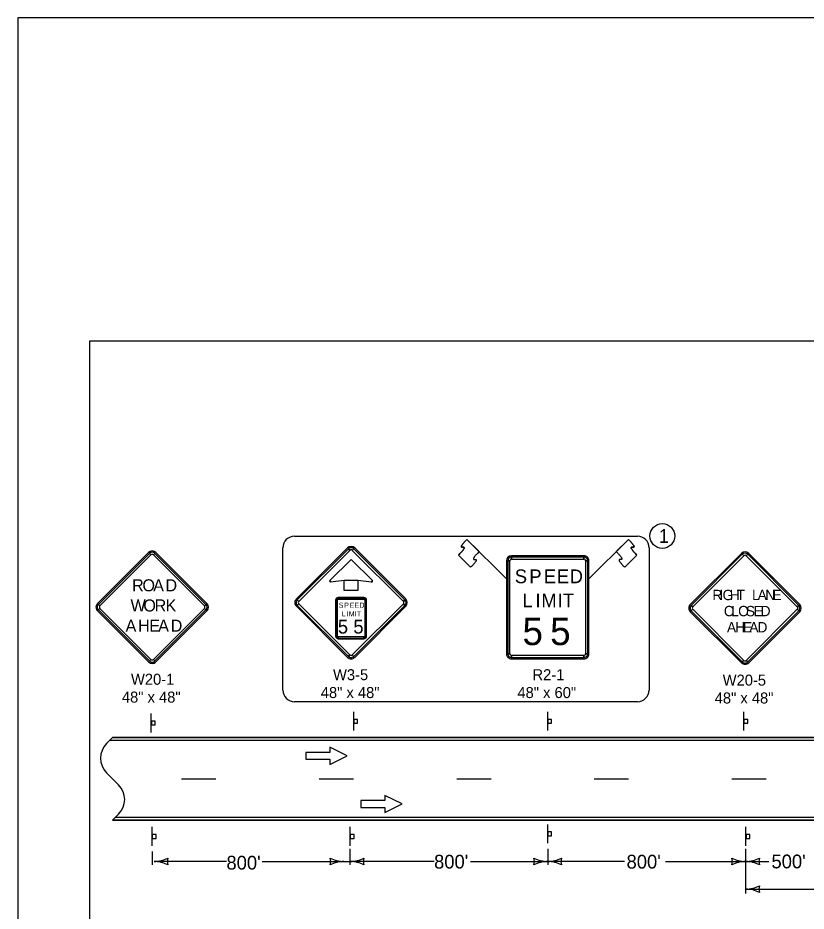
# Model space of a CAD drawing. Extents: x -2135039 to 114557, y -2139150 to -409929.
# Drawn here: x -2131439 to -2130293, y -2137865 to -2136566 of the extents above; entities that cross this region are included whole.
import ezdxf

# ---------------------------------------------------------------- set-up
doc = ezdxf.new("R2010")
doc.units = 0
for name, color, linetype in [('dsnDOTLogo', 7, 'Continuous'), ('dsnStdLabel', 7, 'Continuous'), ('dsnStdLineWork', 7, 'Continuous'), ('dsnStdNote', 7, 'Continuous'), ('dsnStdShading', 7, 'Continuous'), ('Level 1', 7, 'Continuous'), ('StdDimension', 7, 'Continuous')]:
    doc.layers.add(name, color=color, linetype=linetype)

msp = doc.modelspace()

# ---------------------------------------------------------------- linework, layer by layer
at = {"layer": 'dsnDOTLogo'}
msp.add_lwpolyline([(-2131438.9, -2139150.4), (-2128095, -2139150.4), (-2128095, -2136566.4), (-2131438.9, -2136566.4)], close=True, dxfattribs=at)
at = {"layer": 'dsnStdLabel'}
for p, q in [((-2130728.5, -2137382), (-2130785.9, -2137324.7)), ((-2130785.9, -2137324.7), (-2130768.2, -2137342.4)), ((-2130608.5, -2137382), (-2130551.2, -2137324.7)), ((-2130551.2, -2137324.7), (-2130568.9, -2137342.4)), ((-2130959.7, -2137337.2), (-2131034, -2137411.4)), ((-2130958.4, -2137338.5), (-2130956.2, -2137340.7)), ((-2130952.7, -2137340.7), (-2130950.4, -2137338.5)), ((-2130874.9, -2137411.4), (-2130949.1, -2137337.2)), ((-2131248.9, -2137343.8), (-2131323.2, -2137418.1)), ((-2131247.6, -2137345.2), (-2131245.4, -2137347.4)), ((-2131241.9, -2137347.4), (-2131239.6, -2137345.2)), ((-2131164.1, -2137418.1), (-2131238.3, -2137343.8)), ((-2130798.2, -2137347.7), (-2130780.6, -2137365.4)), ((-2130780.6, -2137365.4), (-2130798.2, -2137347.7)), ((-2130616, -2137348.5), (-2130721, -2137348.5)), ((-2130721, -2137353.5), (-2130721, -2137350.4)), ((-2130616, -2137350.4), (-2130616, -2137353.5)), ((-2130538.9, -2137347.7), (-2130556.5, -2137365.4)), ((-2130556.5, -2137365.4), (-2130538.9, -2137347.7)), ((-2130386.9, -2137345.1), (-2130461.2, -2137419.3)), ((-2130385.6, -2137346.4), (-2130383.4, -2137348.6)), ((-2130379.9, -2137348.6), (-2130377.6, -2137346.4)), ((-2130302.1, -2137419.3), (-2130376.3, -2137345.1)), ((-2130728.5, -2137356), (-2130728.5, -2137491)), ((-2130726.7, -2137356), (-2130723.5, -2137356)), ((-2130613.5, -2137356), (-2130610.4, -2137356)), ((-2130608.5, -2137491), (-2130608.5, -2137356)), ((-2130984.4, -2137385.5), (-2130985.3, -2137384.6)), ((-2130984.3, -2137386.7), (-2130984.4, -2137385.5)), ((-2130924.4, -2137385.5), (-2130924.6, -2137386.7)), ((-2130923.5, -2137384.6), (-2130924.4, -2137385.5)), ((-2131030.4, -2137415), (-2131032.6, -2137412.8)), ((-2130976.9, -2137413), (-2130976.9, -2137465.5)), ((-2130976, -2137413), (-2130974.4, -2137413)), ((-2130935.7, -2137409.2), (-2130973.2, -2137409.2)), ((-2130973.2, -2137411.7), (-2130973.2, -2137410.2)), ((-2130935.7, -2137410.2), (-2130935.7, -2137411.7)), ((-2130934.4, -2137413), (-2130932.9, -2137413)), ((-2130931.9, -2137465.5), (-2130931.9, -2137413)), ((-2130876.2, -2137412.8), (-2130878.4, -2137415)), ((-2131323.2, -2137428.7), (-2131248.9, -2137502.9)), ((-2131319.6, -2137421.6), (-2131321.8, -2137419.4)), ((-2131321.8, -2137427.4), (-2131319.6, -2137425.2)), ((-2131238.3, -2137502.9), (-2131164.1, -2137428.7)), ((-2131165.4, -2137419.4), (-2131167.6, -2137421.6)), ((-2131167.6, -2137425.2), (-2131165.4, -2137427.4)), ((-2131034, -2137422), (-2130959.7, -2137496.3)), ((-2131032.6, -2137420.7), (-2131030.4, -2137418.5)), ((-2130949.1, -2137496.3), (-2130874.9, -2137422)), ((-2130878.4, -2137418.5), (-2130876.2, -2137420.7)), ((-2130457.6, -2137422.9), (-2130459.8, -2137420.7)), ((-2130459.8, -2137428.6), (-2130457.6, -2137426.4)), ((-2130303.4, -2137420.7), (-2130305.6, -2137422.9)), ((-2130305.6, -2137426.4), (-2130303.4, -2137428.6)), ((-2130461.2, -2137430), (-2130386.9, -2137504.2)), ((-2130376.3, -2137504.2), (-2130302.1, -2137430)), ((-2130974.4, -2137465.5), (-2130976, -2137465.5)), ((-2130973.2, -2137468.3), (-2130973.2, -2137466.7)), ((-2130935.7, -2137466.7), (-2130935.7, -2137468.3)), ((-2130932.9, -2137465.5), (-2130934.4, -2137465.5)), ((-2130973.2, -2137469.2), (-2130935.7, -2137469.2)), ((-2130956.2, -2137492.8), (-2130958.4, -2137495)), ((-2130950.4, -2137495), (-2130952.7, -2137492.8)), ((-2130723.5, -2137491), (-2130726.7, -2137491)), ((-2130721, -2137496.6), (-2130721, -2137493.5)), ((-2130616, -2137493.5), (-2130616, -2137496.6)), ((-2130610.4, -2137491), (-2130613.5, -2137491)), ((-2131245.4, -2137499.4), (-2131247.6, -2137501.6)), ((-2131239.6, -2137501.6), (-2131241.9, -2137499.4)), ((-2130721, -2137498.5), (-2130616, -2137498.5)), ((-2130383.4, -2137500.7), (-2130385.6, -2137502.9)), ((-2130377.6, -2137502.9), (-2130379.9, -2137500.7)), ((-2131244.9, -2137605.4), (-2131244.9, -2137577.9)), ((-2130950.6, -2137602.9), (-2130950.6, -2137575.4)), ((-2130668.5, -2137602.9), (-2130668.5, -2137575.4)), ((-2130383.4, -2137602.9), (-2130383.4, -2137575.4)), ((-2130668.5, -2137766.7), (-2130668.5, -2137739.2)), ((-2131243.7, -2137770.4), (-2131243.7, -2137742.9)), ((-2130955.7, -2137770.4), (-2130955.7, -2137742.9)), ((-2130380.3, -2137770.4), (-2130380.3, -2137742.9))]:
    msp.add_line(p, q, dxfattribs=at)
for points in [[(-2131036.6, -2137320.1), (-2130538.2, -2137320.1)], [(-2131053.6, -2137543.8), (-2131053.6, -2137337.1)], [(-2130521.2, -2137337.1), (-2130521.2, -2137543.8)], [(-2130538.2, -2137560.8), (-2131036.6, -2137560.8)], [(-2131020.1, -2137634.5), (-2131020.1, -2137644.5), (-2130985.1, -2137644.5), (-2130985.1, -2137652), (-2130960.1, -2137639.5), (-2130985.1, -2137627), (-2130985.1, -2137634.5), (-2131020.1, -2137634.5)], [(-2130940.2, -2137704.5), (-2130940.2, -2137714.5), (-2130905.2, -2137714.5), (-2130905.2, -2137722), (-2130880.2, -2137709.5), (-2130905.2, -2137697), (-2130905.2, -2137704.5), (-2130940.2, -2137704.5)]]:
    msp.add_lwpolyline(points, dxfattribs=at)
for points in [[(-2130958.4, -2137338.5), (-2131032.6, -2137412.8), (-2131030.4, -2137415), (-2130956.2, -2137340.7), (-2130958.4, -2137338.5)], [(-2130876.2, -2137412.8), (-2130950.4, -2137338.5), (-2130952.7, -2137340.7), (-2130878.4, -2137415), (-2130876.2, -2137412.8)], [(-2131247.6, -2137345.2), (-2131321.8, -2137419.4), (-2131319.6, -2137421.6), (-2131245.4, -2137347.4), (-2131247.6, -2137345.2)], [(-2131165.4, -2137419.4), (-2131239.6, -2137345.2), (-2131241.9, -2137347.4), (-2131167.6, -2137421.6), (-2131165.4, -2137419.4)], [(-2130616, -2137350.4), (-2130721, -2137350.4), (-2130721, -2137353.5), (-2130616, -2137353.5), (-2130616, -2137350.4)], [(-2130385.6, -2137346.4), (-2130459.8, -2137420.7), (-2130457.6, -2137422.9), (-2130383.4, -2137348.6), (-2130385.6, -2137346.4)], [(-2130303.4, -2137420.7), (-2130377.6, -2137346.4), (-2130379.9, -2137348.6), (-2130305.6, -2137422.9), (-2130303.4, -2137420.7)], [(-2130954.4, -2137354.2), (-2130985.3, -2137384.6), (-2130984.4, -2137385.5), (-2130984.3, -2137386.7), (-2130964.4, -2137384.2), (-2130944.4, -2137384.2), (-2130924.6, -2137386.7), (-2130924.4, -2137385.5), (-2130923.5, -2137384.6), (-2130954.4, -2137354.2)], [(-2130726.7, -2137356), (-2130726.7, -2137491), (-2130723.5, -2137491), (-2130723.5, -2137356), (-2130726.7, -2137356)], [(-2130610.4, -2137491), (-2130610.4, -2137356), (-2130613.5, -2137356), (-2130613.5, -2137491), (-2130610.4, -2137491)], [(-2130944.4, -2137399.2), (-2130964.4, -2137399.2), (-2130964.4, -2137384.2), (-2130944.4, -2137384.2), (-2130944.4, -2137399.2)], [(-2130976, -2137413), (-2130976, -2137465.5), (-2130974.4, -2137465.5), (-2130974.4, -2137413), (-2130976, -2137413)], [(-2130935.7, -2137410.2), (-2130973.2, -2137410.2), (-2130973.2, -2137411.7), (-2130935.7, -2137411.7), (-2130935.7, -2137410.2)], [(-2130932.9, -2137465.5), (-2130932.9, -2137413), (-2130934.4, -2137413), (-2130934.4, -2137465.5), (-2130932.9, -2137465.5)], [(-2131321.8, -2137427.4), (-2131247.6, -2137501.6), (-2131245.4, -2137499.4), (-2131319.6, -2137425.2), (-2131321.8, -2137427.4)], [(-2131239.6, -2137501.6), (-2131165.4, -2137427.4), (-2131167.6, -2137425.2), (-2131241.9, -2137499.4), (-2131239.6, -2137501.6)], [(-2131032.6, -2137420.7), (-2130958.4, -2137495), (-2130956.2, -2137492.8), (-2131030.4, -2137418.5), (-2131032.6, -2137420.7)], [(-2130950.4, -2137495), (-2130876.2, -2137420.7), (-2130878.4, -2137418.5), (-2130952.7, -2137492.8), (-2130950.4, -2137495)], [(-2130459.8, -2137428.6), (-2130385.6, -2137502.9), (-2130383.4, -2137500.7), (-2130457.6, -2137426.4), (-2130459.8, -2137428.6)], [(-2130377.6, -2137502.9), (-2130303.4, -2137428.6), (-2130305.6, -2137426.4), (-2130379.9, -2137500.7), (-2130377.6, -2137502.9)], [(-2130973.2, -2137468.3), (-2130935.7, -2137468.3), (-2130935.7, -2137466.7), (-2130973.2, -2137466.7), (-2130973.2, -2137468.3)], [(-2130721, -2137496.6), (-2130616, -2137496.6), (-2130616, -2137493.5), (-2130721, -2137493.5), (-2130721, -2137496.6)], [(-2131244.8, -2137589), (-2131244.8, -2137594.6), (-2131239.2, -2137594.6), (-2131239.2, -2137589)], [(-2130950.5, -2137586.5), (-2130950.5, -2137592.1), (-2130944.9, -2137592.1), (-2130944.9, -2137586.5)], [(-2130668.5, -2137586.5), (-2130668.5, -2137592.1), (-2130662.8, -2137592.1), (-2130662.8, -2137586.5)], [(-2130383.3, -2137586.5), (-2130383.3, -2137592.1), (-2130377.7, -2137592.1), (-2130377.7, -2137586.5)], [(-2131243.6, -2137754), (-2131243.6, -2137759.6), (-2131238, -2137759.6), (-2131238, -2137754)], [(-2130955.6, -2137754), (-2130955.6, -2137759.6), (-2130950, -2137759.6), (-2130950, -2137754)], [(-2130668.4, -2137750.2), (-2130668.4, -2137755.8), (-2130662.8, -2137755.8), (-2130662.8, -2137750.2)], [(-2130380.2, -2137754), (-2130380.2, -2137759.6), (-2130374.6, -2137759.6), (-2130374.6, -2137754)]]:
    msp.add_lwpolyline(points, close=True, dxfattribs=at)
for centre, radius, start, end in [((-2131036.6, -2137337.1), 17, 90, 180), ((-2130538.2, -2137337.1), 17, 0, 90), ((-2130954.4, -2137342.5), 7.5, 45, 134.9997), ((-2130954.4, -2137342.5), 5.62, 45, 134.9997), ((-2131243.6, -2137349.1), 7.5, 45, 134.9997), ((-2131243.6, -2137349.1), 5.62, 45, 134.9997), ((-2131243.6, -2137349.1), 2.5, 45, 134.9997), ((-2130954.4, -2137342.5), 2.5, 45, 134.9997), ((-2130721, -2137356), 7.5, 90.0002, 179.9998), ((-2130721, -2137356), 5.62, 90.0002, 179.9998), ((-2130616, -2137356), 7.5, 0, 90.0002), ((-2130616, -2137356), 5.62, 0, 90.0002), ((-2130381.6, -2137350.4), 7.5, 45, 134.9997), ((-2130381.6, -2137350.4), 5.62, 45, 134.9997), ((-2130381.6, -2137350.4), 2.5, 45, 134.9997), ((-2130721, -2137356), 2.5, 90.0002, 179.9998), ((-2130616, -2137356), 2.5, 0, 90.0002), ((-2130984.4, -2137385.5), 1.25, 134.9997, 277.1529), ((-2130924.4, -2137385.5), 1.25, 262.8473, 44.9998), ((-2131028.7, -2137416.7), 7.5, 134.9997, 225), ((-2131028.7, -2137416.7), 5.62, 134.9997, 225), ((-2131028.7, -2137416.7), 2.5, 134.9997, 225), ((-2130973.2, -2137413), 3.75, 90.0002, 179.9998), ((-2130973.2, -2137413), 2.81, 90.0002, 179.9998), ((-2130973.2, -2137413), 1.25, 90.0002, 179.9998), ((-2130935.7, -2137413), 3.75, 0, 90.0002), ((-2130935.7, -2137413), 2.81, 0, 90.0002), ((-2130935.7, -2137413), 1.25, 0, 90.0002), ((-2130880.2, -2137416.7), 2.5, 315.0002, 44.9998), ((-2130880.2, -2137416.7), 5.62, 315.0002, 44.9998), ((-2130880.2, -2137416.7), 7.5, 315.0002, 44.9998), ((-2131317.9, -2137423.4), 7.5, 134.9997, 225), ((-2131317.9, -2137423.4), 5.62, 134.9997, 225), ((-2131317.9, -2137423.4), 2.5, 134.9997, 225), ((-2131169.4, -2137423.4), 2.5, 315.0002, 44.9998), ((-2131169.4, -2137423.4), 5.62, 315.0002, 44.9998), ((-2131169.4, -2137423.4), 7.5, 315.0002, 44.9998), ((-2130455.9, -2137424.7), 7.5, 134.9997, 225), ((-2130455.9, -2137424.7), 5.62, 134.9997, 225), ((-2130455.9, -2137424.7), 2.5, 134.9997, 225), ((-2130307.4, -2137424.7), 2.5, 315.0002, 44.9998), ((-2130307.4, -2137424.7), 5.62, 315.0002, 44.9998), ((-2130307.4, -2137424.7), 7.5, 315.0002, 44.9998), ((-2130973.2, -2137465.5), 3.75, 179.9998, 270.0001), ((-2130973.2, -2137465.5), 2.81, 179.9998, 270.0001), ((-2130973.2, -2137465.5), 1.25, 179.9998, 270.0001), ((-2130935.7, -2137465.5), 3.75, 270.0001, 0.0003), ((-2130935.7, -2137465.5), 2.81, 270.0001, 0.0003), ((-2130935.7, -2137465.5), 1.25, 270.0001, 0.0003), ((-2130954.4, -2137491), 2.5, 225, 315.0002), ((-2130721, -2137491), 7.5, 179.9998, 270.0001), ((-2130721, -2137491), 5.62, 179.9998, 270.0001), ((-2130721, -2137491), 2.5, 179.9998, 270.0001), ((-2130616, -2137491), 7.5, 270.0001, 0.0003), ((-2130616, -2137491), 5.62, 270.0001, 0.0003), ((-2130616, -2137491), 2.5, 270.0001, 0.0003), ((-2131243.6, -2137497.6), 7.5, 225, 315.0002), ((-2131243.6, -2137497.6), 5.62, 225, 315.0002), ((-2131243.6, -2137497.6), 2.5, 225, 315.0002), ((-2130954.4, -2137491), 7.5, 225, 315.0002), ((-2130954.4, -2137491), 5.62, 225, 315.0002), ((-2130381.6, -2137498.9), 7.5, 225, 315.0002), ((-2130381.6, -2137498.9), 5.62, 225, 315.0002), ((-2130381.6, -2137498.9), 2.5, 225, 315.0002), ((-2131036.6, -2137543.8), 17, 180, 270), ((-2130538.2, -2137543.8), 17, 270, 0)]:
    msp.add_arc(centre, radius, start, end, dxfattribs=at)
for points in [[(-2130785.9, -2137324.7), (-2130798.2, -2137337.1), (-2130785.9, -2137335.3), (-2130798.2, -2137347.7)], [(-2130798.2, -2137347.7), (-2130785.9, -2137335.3), (-2130798.2, -2137337.1), (-2130785.9, -2137324.7)], [(-2130551.2, -2137324.7), (-2130538.9, -2137337.1), (-2130551.2, -2137335.3), (-2130538.9, -2137347.7)], [(-2130538.9, -2137347.7), (-2130551.2, -2137335.3), (-2130538.9, -2137337.1), (-2130551.2, -2137324.7)], [(-2130768.2, -2137342.4), (-2130780.6, -2137354.8), (-2130768.2, -2137353), (-2130780.6, -2137365.4)], [(-2130768.2, -2137342.4), (-2130780.6, -2137354.8), (-2130768.2, -2137353), (-2130780.6, -2137365.4)], [(-2130568.9, -2137342.4), (-2130556.5, -2137354.8), (-2130568.9, -2137353), (-2130556.5, -2137365.4)], [(-2130568.9, -2137342.4), (-2130556.5, -2137354.8), (-2130568.9, -2137353), (-2130556.5, -2137365.4)]]:
    msp.add_open_spline(points, degree=2, dxfattribs=at)
at = {"layer": 'dsnStdLineWork'}
for p, q in [((-2131301.2, -2137612.9), (-2131310, -2137621.7)), ((-2131310, -2137664.1), (-2131292.4, -2137681.7)), ((-2131292.4, -2137724.1), (-2131301.2, -2137732.9)), ((-2131297.2, -2137728.9), (-2129682, -2137728.9))]:
    msp.add_line(p, q, dxfattribs=at)
for points in [[(-2131305.2, -2137616.9), (-2129275.6, -2137616.9)], [(-2131200.9, -2137672.9), (-2131150.9, -2137672.9)], [(-2131000.9, -2137672.9), (-2130950.9, -2137672.9)], [(-2130800.9, -2137672.9), (-2130750.9, -2137672.9)], [(-2130600.9, -2137672.9), (-2130551, -2137672.9)], [(-2130401, -2137672.9), (-2130351, -2137672.9)]]:
    msp.add_lwpolyline(points, dxfattribs=at)
for centre, start, end in [((-2131288.8, -2137642.9), 135, 225), ((-2131313.6, -2137702.9), 315, 45)]:
    msp.add_arc(centre, 30, start, end, dxfattribs=at)
at = {"layer": 'dsnStdNote'}
msp.add_circle((-2130501.8, -2137319.8), 18, dxfattribs=at)
at = {"layer": 'dsnStdShading'}
for p, q in [((-2131310, -2137621.7), (-2131305.2, -2137616.9)), ((-2131301.2, -2137612.9), (-2131305.2, -2137616.9)), ((-2131305.2, -2137616.9), (-2130088, -2137616.9)), ((-2131305.2, -2137616.9), (-2129509.7, -2137616.9)), ((-2131301.2, -2137612.9), (-2129174.6, -2137612.9)), ((-2129511.4, -2137612.9), (-2131301.2, -2137612.9)), ((-2131292.4, -2137681.7), (-2131310, -2137664.1)), ((-2131301.2, -2137732.9), (-2131292.4, -2137724.1)), ((-2131301.2, -2137732.9), (-2128969, -2137732.9)), ((-2130256.8, -2137732.9), (-2131301.2, -2137732.9))]:
    msp.add_line(p, q, dxfattribs=at)
msp.add_lwpolyline([(-2131305.2, -2137616.9), (-2131305.2, -2137616.9)], dxfattribs=at)
msp.add_lwpolyline([(-2131305.2, -2137616.9), (-2131305.2, -2137616.9)], dxfattribs=at)
for centre, start, end in [((-2131288.8, -2137642.9), 135, 225), ((-2131313.6, -2137702.9), 315, 45)]:
    msp.add_arc(centre, 30, start, end, dxfattribs=at)
at = {"layer": 'Level 1'}
msp.add_lwpolyline([(-2131334.4, -2137035.9), (-2128199.5, -2137035.9), (-2128199.5, -2139045.9), (-2131334.4, -2139045.9)], close=True, dxfattribs=at)
at = {"layer": 'StdDimension'}
for p, q in [((-2131243.7, -2137778.4), (-2131243.7, -2137798.1)), ((-2130956.1, -2137774.7), (-2130956.1, -2137798.1)), ((-2130668.5, -2137774.7), (-2130668.5, -2137798.1)), ((-2130668.5, -2137778.4), (-2130668.5, -2137798.1)), ((-2130380.9, -2137774.7), (-2130380.9, -2137839.5)), ((-2131135.5, -2137793.1), (-2131240.9, -2137793.1)), ((-2131083.6, -2137793.1), (-2130956.1, -2137793.1)), ((-2130833.7, -2137793.1), (-2130956.1, -2137793.1)), ((-2130781, -2137793.1), (-2130668.5, -2137793.1)), ((-2130556.7, -2137793.1), (-2130668.5, -2137793.1)), ((-2130497.3, -2137793.1), (-2130380.9, -2137793.1)), ((-2130380.1, -2137793.1), (-2130347.1, -2137793.1)), ((-2130380.9, -2137833.3), (-2130260.2, -2137833.3))]:
    msp.add_line(p, q, dxfattribs=at)
for centre, radius, start, end in [((-2131240.9, -2137750.6), 42.5, 270, 298.0725), ((-2131240.9, -2137835.6), 42.5, 61.9275, 90), ((-2131205.2, -2137793.1), 16.4, 162.2666, 197.7334), ((-2131000.5, -2137793.1), 16.4, 342.2667, 17.7334), ((-2130964.8, -2137750.6), 42.5, 241.9275, 270), ((-2130964.8, -2137835.6), 42.5, 90, 118.0725), ((-2130955.7, -2137750.6), 42.5, 270, 298.0725), ((-2130955.7, -2137835.6), 42.5, 61.9275, 90), ((-2130920.1, -2137793.1), 16.4, 162.2666, 197.7334), ((-2130704.2, -2137793.1), 16.4, 342.2667, 17.7334), ((-2130668.5, -2137750.6), 42.5, 241.9275, 270), ((-2130668.5, -2137835.6), 42.5, 90, 118.0725), ((-2130668.5, -2137750.6), 42.5, 270, 298.0725), ((-2130668.5, -2137835.6), 42.5, 61.9275, 90), ((-2130632.9, -2137793.1), 16.4, 162.2666, 197.7334), ((-2130416.4, -2137793.1), 16.4, 342.2667, 17.7334), ((-2130380.7, -2137750.6), 42.5, 241.9275, 270), ((-2130380.7, -2137835.6), 42.5, 90, 118.0725), ((-2130380.7, -2137750.6), 42.5, 270, 298.0725), ((-2130380.7, -2137835.6), 42.5, 61.9275, 90), ((-2130345.1, -2137793.1), 16.4, 162.2666, 197.7334), ((-2130380.7, -2137790.8), 42.5, 270, 298.0725), ((-2130345.1, -2137833.3), 16.4, 162.2666, 197.7334), ((-2130380.7, -2137875.8), 42.5, 61.9275, 90)]:
    msp.add_arc(centre, radius, start, end, dxfattribs=at)

# ---------------------------------------------------------------- texts
at = {"layer": 'dsnStdLabel'}
for s, height, p in [('S', 20, (-2130716.4, -2137388.5)), ('P', 20, (-2130695.3, -2137388.5)), ('E', 20, (-2130674.2, -2137388.5)), ('E', 20, (-2130655.4, -2137388.5)), ('D', 20, (-2130636.6, -2137388.5)), ('R', 17.5, (-2131272.8, -2137400.3)), ('O', 17.5, (-2131257.8, -2137400.3)), ('A', 17.5, (-2131242.2, -2137400.3)), ('D', 17.5, (-2131224.3, -2137400.3)), ('L', 20, (-2130705.2, -2137423.5)), ('I', 20, (-2130686.4, -2137423.5)), ('M', 20, (-2130677.8, -2137423.5)), ('I', 20, (-2130654.2, -2137423.5)), ('T', 20, (-2130646.6, -2137423.5)), ('R', 15, (-2130429.1, -2137413.1)), ('I', 15, (-2130418.7, -2137413.1)), ('G', 15, (-2130414.3, -2137413.1)), ('H', 15, (-2130403.9, -2137413.1)), ('T', 15, (-2130393.9, -2137413.1)), ('L', 15, (-2130371.4, -2137413.1)), ('A', 15, (-2130363.3, -2137413.1)), ('N', 15, (-2130352.1, -2137413.1)), ('E', 15, (-2130341.6, -2137413.1)), ('W', 17.5, (-2131275.1, -2137429.6)), ('O', 17.5, (-2131256.5, -2137429.6)), ('R', 17.5, (-2131240.1, -2137429.6)), ('K', 17.5, (-2131224.2, -2137429.6)), ('S', 7.5, (-2130972.4, -2137424.2)), ('L', 7.5, (-2130968.2, -2137436.7)), ('P', 7.5, (-2130964.5, -2137424.2)), ('I', 7.5, (-2130961.1, -2137436.7)), ('M', 7.5, (-2130957.9, -2137436.7)), ('E', 7.5, (-2130956.6, -2137424.2)), ('E', 7.5, (-2130949.5, -2137424.2)), ('I', 7.5, (-2130949, -2137436.7)), ('T', 7.5, (-2130946.2, -2137436.7)), ('D', 7.5, (-2130942.4, -2137424.2)), ('C', 15, (-2130412.4, -2137436.5)), ('L', 15, (-2130401.7, -2137436.5)), ('O', 15, (-2130391.6, -2137436.5)), ('S', 15, (-2130380.4, -2137436.5)), ('E', 15, (-2130369.1, -2137436.5)), ('D', 15, (-2130359, -2137436.5)), ('A', 17.5, (-2131282.3, -2137459)), ('H', 17.5, (-2131264.1, -2137459)), ('E', 17.5, (-2131247.9, -2137459)), ('A', 17.5, (-2131234.9, -2137459)), ('D', 17.5, (-2131216.7, -2137459)), ('5', 20, (-2130973.7, -2137461.7)), ('5', 20, (-2130951.1, -2137461.7)), ('5', 40, (-2130705.2, -2137478.5)), ('5', 40, (-2130665, -2137478.5)), ('A', 15, (-2130407.9, -2137460)), ('H', 15, (-2130396, -2137460)), ('E', 15, (-2130384.6, -2137460)), ('A', 15, (-2130375.5, -2137460)), ('D', 15, (-2130363.6, -2137460)), ('W20-1', 16, (-2131274.5, -2137536.1)), ('W3-5', 16, (-2130980.7, -2137529.5)), ('R2-1', 16, (-2130690.7, -2137529.5)), ('W20-5', 16, (-2130414.1, -2137537.4)), ('48" x 48"', 16, (-2131287.7, -2137562.1)), ('48" x 48"', 16, (-2130998.5, -2137555.5)), ('48" x 60"', 16, (-2130712.6, -2137555.5)), ('48" x 48"', 16, (-2130425.7, -2137563.4))]:
    msp.add_text(s, height=height, dxfattribs=at).set_placement(p)
at = {"layer": 'dsnStdNote'}
msp.add_text('1', height=20, dxfattribs=at).set_placement((-2130507, -2137329.8))
at = {"layer": 'StdDimension'}
for s, p in [("800'", (-2131135.7, -2137804.9)), ("800'", (-2130833.8, -2137803.4)), ("800'", (-2130553.9, -2137803.4)), ("500'", (-2130343.2, -2137803.1))]:
    msp.add_text(s, height=20, dxfattribs=at).set_placement(p)

doc.saveas('drawing.dxf')
